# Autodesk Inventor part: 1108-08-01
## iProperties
Created: 2007-03
Part Number: 1108-08-01
Document SubType Name: Modeling
Designer: Andy Moles
Material: Steel
Mass: 25.469 g
Surface Area: 31.4225 cm^2
Volume: 3.24446 cm^3
Density: 7.85 g/cm^3
Author: Andy Moles
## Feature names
1. Base1
